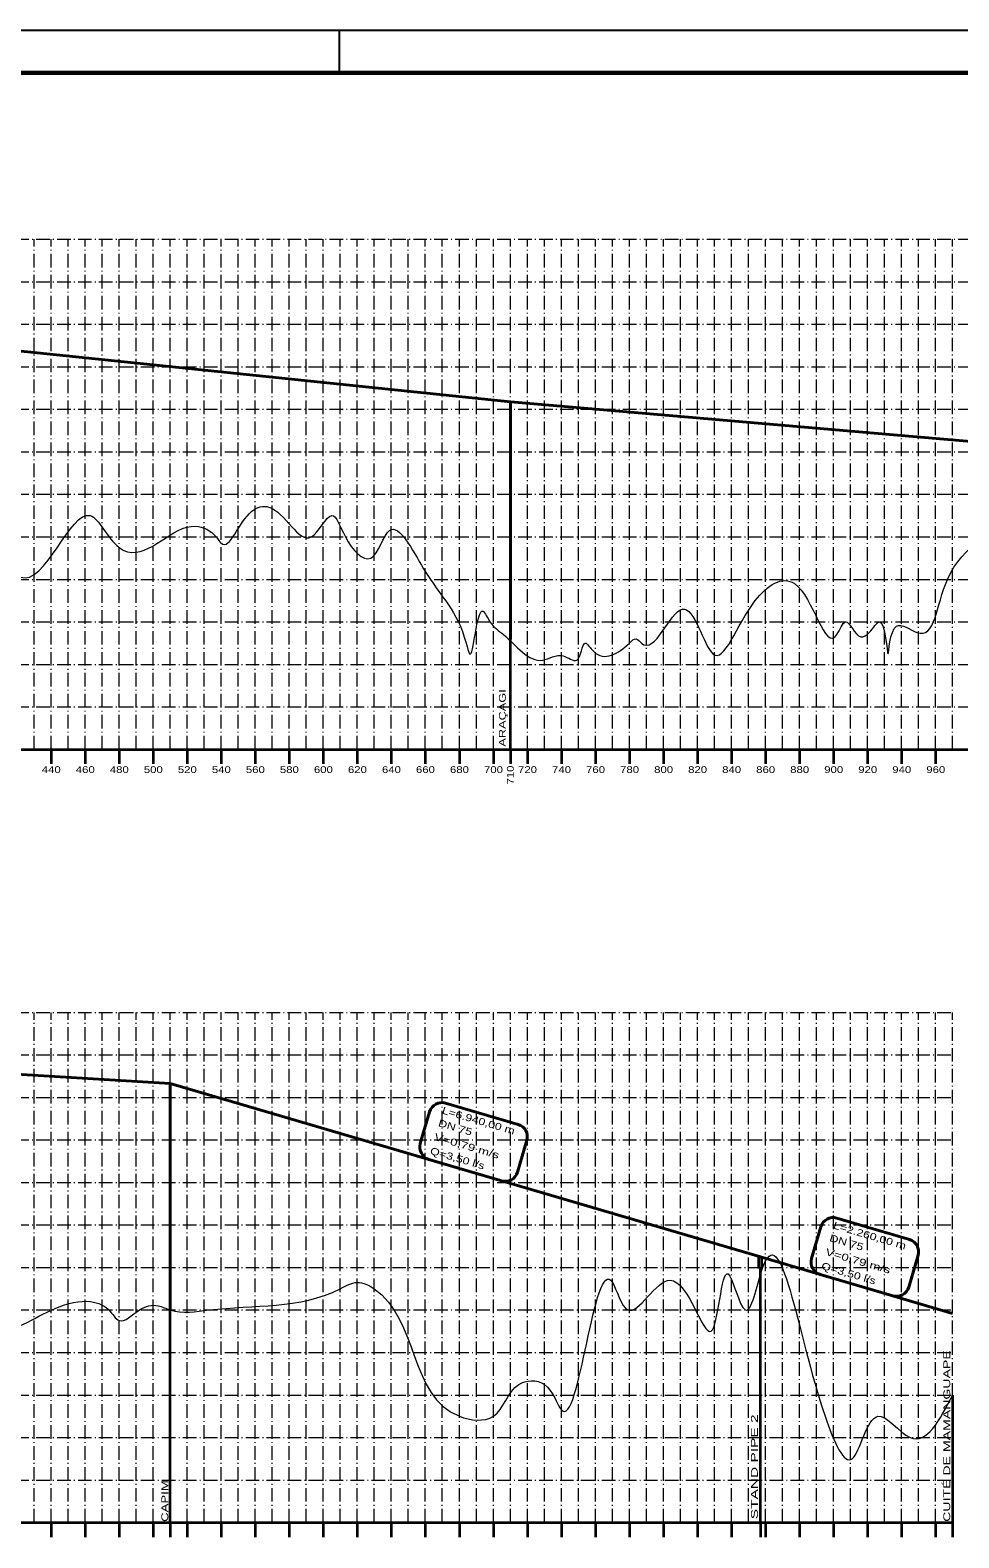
# Model space of a CAD drawing. Extents: x -4 to 42046, y -3 to 29697.
# Drawn here: x 11660 to 22579, y 11967 to 29697 of the extents above; entities that cross this region are included whole.
import ezdxf
from ezdxf.enums import TextEntityAlignment as Align

# ---------------------------------------------------------------- set-up
doc = ezdxf.new("R2010")
doc.units = 0
doc.header["$LTSCALE"] = 32
doc.linetypes.add('DOT_DASHED', pattern=[7.7, 5, -1.2, 0.3, -1.2])
for name, color, linetype, lineweight in [('1', 7, 'DOT_DASHED', 13), ('24', 7, 'Continuous', 35), ('55', 7, 'Continuous', 13), ('62', 7, 'Continuous', 13), ('63', 7, 'Continuous', 25), ('7', 7, 'Continuous', 35), ('9', 7, 'Continuous', 40)]:
    doc.layers.add(name, color=color, linetype=linetype, lineweight=lineweight)

msp = doc.modelspace()

# ---------------------------------------------------------------- linework, layer by layer
at = {"layer": '1'}
for p, q in [((3105.77, 27238.44), (32905.77, 27238.44)), ((11705.77, 21238.44), (11705.77, 27238.44)), ((11905.77, 21238.44), (11905.77, 27238.44)), ((12105.77, 21238.44), (12105.77, 27238.44)), ((12305.77, 21238.44), (12305.77, 27238.44)), ((12505.77, 21238.44), (12505.77, 27238.44)), ((12705.77, 21238.44), (12705.77, 27238.44)), ((12905.77, 21238.44), (12905.77, 27238.44)), ((13105.77, 21238.44), (13105.77, 27238.44)), ((13305.77, 21238.44), (13305.77, 27238.44)), ((13505.77, 21238.44), (13505.77, 27238.44)), ((13705.77, 21238.44), (13705.77, 27238.44)), ((13905.77, 21238.44), (13905.77, 27238.44)), ((14105.77, 21238.44), (14105.77, 27238.44)), ((14305.77, 21238.44), (14305.77, 27238.44)), ((14505.77, 21238.44), (14505.77, 27238.44)), ((14705.77, 21238.44), (14705.77, 27238.44)), ((14905.77, 21238.44), (14905.77, 27238.44)), ((15105.77, 21238.44), (15105.77, 27238.44)), ((15305.77, 21238.44), (15305.77, 27238.44)), ((15505.77, 21238.44), (15505.77, 27238.44)), ((15705.77, 21238.44), (15705.77, 27238.44)), ((15905.77, 21238.44), (15905.77, 27238.44)), ((16105.77, 21238.44), (16105.77, 27238.44)), ((16305.77, 21238.44), (16305.77, 27238.44)), ((16505.77, 21238.44), (16505.77, 27238.44)), ((16705.77, 21238.44), (16705.77, 27238.44)), ((16905.77, 21238.44), (16905.77, 27238.44)), ((17105.77, 21238.44), (17105.77, 27238.44)), ((17305.77, 21238.44), (17305.77, 27238.44)), ((17505.77, 21238.44), (17505.77, 27238.44)), ((17705.77, 21238.44), (17705.77, 27238.44)), ((17905.77, 21238.44), (17905.77, 27238.44)), ((18105.77, 21238.44), (18105.77, 27238.44)), ((18305.77, 21238.44), (18305.77, 27238.44)), ((18505.77, 21238.44), (18505.77, 27238.44)), ((18705.77, 21238.44), (18705.77, 27238.44)), ((18905.77, 21238.44), (18905.77, 27238.44)), ((19105.77, 21238.44), (19105.77, 27238.44)), ((19305.77, 21238.44), (19305.77, 27238.44)), ((19505.77, 21238.44), (19505.77, 27238.44)), ((19705.77, 21238.44), (19705.77, 27238.44)), ((19905.77, 21238.44), (19905.77, 27238.44)), ((20105.77, 21238.44), (20105.77, 27238.44)), ((20305.77, 21238.44), (20305.77, 27238.44)), ((20505.77, 21238.44), (20505.77, 27238.44)), ((20705.77, 21238.44), (20705.77, 27238.44)), ((20905.77, 21238.44), (20905.77, 27238.44)), ((21105.77, 21238.44), (21105.77, 27238.44)), ((21305.77, 21238.44), (21305.77, 27238.44)), ((21505.77, 21238.44), (21505.77, 27238.44)), ((21705.77, 21238.44), (21705.77, 27238.44)), ((21905.77, 21238.44), (21905.77, 27238.44)), ((22105.77, 21238.44), (22105.77, 27238.44)), ((22305.77, 21238.44), (22305.77, 27238.44)), ((22505.77, 21238.44), (22505.77, 27238.44)), ((3105.77, 26738.44), (32905.77, 26738.44)), ((3105.77, 26238.44), (32905.77, 26238.44)), ((3105.77, 25738.44), (32905.77, 25738.44)), ((3105.77, 25238.44), (32905.77, 25238.44)), ((3105.77, 24738.44), (32905.77, 24738.44)), ((3105.77, 24238.44), (32905.77, 24238.44)), ((3105.77, 23738.44), (32905.77, 23738.44)), ((3105.77, 23238.44), (32905.77, 23238.44)), ((3105.77, 22738.44), (32905.77, 22738.44)), ((3105.77, 22238.44), (32905.77, 22238.44)), ((3105.77, 21738.44), (32905.77, 21738.44)), ((3105.77, 18146.17), (22505.77, 18146.17)), ((11705.77, 12146.17), (11705.77, 18146.17)), ((11905.77, 12146.17), (11905.77, 18146.17)), ((12105.77, 12146.17), (12105.77, 18146.17)), ((12305.77, 12146.17), (12305.77, 18146.17)), ((12505.77, 12146.17), (12505.77, 18146.17)), ((12705.77, 12146.17), (12705.77, 18146.17)), ((12905.77, 12146.17), (12905.77, 18146.17)), ((13105.77, 12146.17), (13105.77, 18146.17)), ((13305.77, 12146.17), (13305.77, 18146.17)), ((13505.77, 12146.17), (13505.77, 18146.17)), ((13705.77, 12146.17), (13705.77, 18146.17)), ((13905.77, 12146.17), (13905.77, 18146.17)), ((14105.77, 12146.17), (14105.77, 18146.17)), ((14305.77, 12146.17), (14305.77, 18146.17)), ((14505.77, 12146.17), (14505.77, 18146.17)), ((14705.77, 12146.17), (14705.77, 18146.17)), ((14905.77, 12146.17), (14905.77, 18146.17)), ((15105.77, 12146.17), (15105.77, 18146.17)), ((15305.77, 12146.17), (15305.77, 18146.17)), ((15505.77, 12146.17), (15505.77, 18146.17)), ((15705.77, 12146.17), (15705.77, 18146.17)), ((15905.77, 12146.17), (15905.77, 18146.17)), ((16105.77, 12146.17), (16105.77, 18146.17)), ((16305.77, 12146.17), (16305.77, 18146.17)), ((16505.77, 12146.17), (16505.77, 18146.17)), ((16705.77, 12146.17), (16705.77, 18146.17)), ((16905.77, 12146.17), (16905.77, 18146.17)), ((17105.77, 12146.17), (17105.77, 18146.17)), ((17305.77, 12146.17), (17305.77, 18146.17)), ((17505.77, 12146.17), (17505.77, 18146.17)), ((17705.77, 12146.17), (17705.77, 18146.17)), ((17905.77, 12146.17), (17905.77, 18146.17)), ((18105.77, 12146.17), (18105.77, 18146.17)), ((18305.77, 12146.17), (18305.77, 18146.17)), ((18505.77, 12146.17), (18505.77, 18146.17)), ((18705.77, 12146.17), (18705.77, 18146.17)), ((18905.77, 12146.17), (18905.77, 18146.17)), ((19105.77, 12146.17), (19105.77, 18146.17)), ((19305.77, 12146.17), (19305.77, 18146.17)), ((19505.77, 12146.17), (19505.77, 18146.17)), ((19705.77, 12146.17), (19705.77, 18146.17)), ((19905.77, 12146.17), (19905.77, 18146.17)), ((20105.77, 12146.17), (20105.77, 18146.17)), ((20305.77, 12146.17), (20305.77, 18146.17)), ((20505.77, 12146.17), (20505.77, 18146.17)), ((20705.77, 12146.17), (20705.77, 18146.17)), ((20905.77, 12146.17), (20905.77, 18146.17)), ((21105.77, 12146.17), (21105.77, 18146.17)), ((21305.77, 12146.17), (21305.77, 18146.17)), ((21505.77, 12146.17), (21505.77, 18146.17)), ((21705.77, 12146.17), (21705.77, 18146.17)), ((21905.77, 12146.17), (21905.77, 18146.17)), ((22105.77, 12146.17), (22105.77, 18146.17)), ((22305.77, 12146.17), (22305.77, 18146.17)), ((22505.77, 12146.17), (22505.77, 18146.17)), ((3105.77, 17646.17), (22505.77, 17646.17)), ((3105.77, 17146.17), (22505.77, 17146.17)), ((3105.77, 16646.17), (22505.77, 16646.17)), ((3105.77, 16146.17), (22505.77, 16146.17)), ((3105.77, 15646.17), (22505.77, 15646.17)), ((3105.77, 15146.17), (22505.77, 15146.17)), ((3105.77, 14646.17), (22505.77, 14646.17)), ((3105.77, 14146.17), (22505.77, 14146.17)), ((3105.77, 13646.17), (22505.77, 13646.17)), ((3105.77, 13146.17), (22505.77, 13146.17)), ((3105.77, 12646.17), (22505.77, 12646.17))]:
    msp.add_line(p, q, dxfattribs=at)
at = {"layer": '24'}
for p, q in [((20245.77, 12146.17), (20245.77, 15146.53)), ((13305.77, 12146.17), (13305.77, 14646.17))]:
    msp.add_line(p, q, dxfattribs=at)
at = {"layer": '55'}
for points in [[(3105.77, 22363.44), (3345.77, 22238.44), (3395.77, 22113.44), (3445.77, 22238.44), (3485.77, 22488.44), (3525.77, 22238.44), (3676.64, 22756.56), (3717.19, 22944.93), (3805.77, 23063.44), (3905.77, 22738.44), (3965.77, 22363.44), (4225.77, 23188.44), (4625.77, 22988.44), (5145.77, 21963.44), (6165.77, 22963.44), (6365.77, 22738.44), (6545.77, 22988.44), (6945.77, 23088.44), (7145.77, 23188.44), (7685.77, 23188.44), (8005.77, 22988.44), (8205.77, 22488.44), (8245.77, 22613.44), (8285.77, 22488.44), (8705.77, 22113.44), (9065.77, 22738.44), (9685.77, 23288.44), (10205.77, 23238.44), (10545.77, 23313.44), (11345.77, 23413.44), (11545.77, 23263.44), (12365.77, 23988.44), (12705.77, 23613.44), (12805.77, 23563.44), (13605.77, 23863.44), (13845.77, 23738.44), (13905.77, 23663.44), (14265.77, 24038.44), (14465.77, 24088.44), (14965.77, 23738.44), (15205.77, 23988.44), (15365.77, 23738.44), (15665.77, 23488.44), (15885.77, 23813.44), (16285.77, 23363.44), (16785.77, 22488.44), (16825.77, 22363.44), (16985.77, 22863.44), (17065.77, 22738.44), (17225.77, 22588.44), (17685.77, 22288.44), (17925.77, 22338.44), (18085.77, 22288.44), (18185.77, 22488.44), (18285.77, 22388.44), (18705.77, 22488.44), (18785.77, 22538.44), (18845.77, 22488.44), (19325.77, 22888.44), (19685.77, 22363.44), (20185.77, 22988.44), (20645.77, 23188.44), (21145.77, 22588.44), (21245.77, 22738.44), (21425.77, 22563.44), (21525.77, 22613.44), (21645.77, 22738.44), (21745.77, 22363.44), (21845.77, 22688.44), (22085.77, 22613.44), (22445.77, 23238.44), (23265.77, 23663.44), (23585.77, 23313.44), (23905.77, 23563.44), (24365.77, 23413.44), (24725.77, 23613.44), (25545.77, 23113.44), (26045.77, 23613.44), (27245.77, 23988.44), (27705.77, 23563.44), (27905.77, 23738.44), (28085.77, 23588.44), (28605.77, 24113.44), (29205.77, 23638.44), (29325.77, 23738.44), (29405.77, 23563.44)], [(3105.77, 13671.17), (3465.77, 13796.17), (4045.77, 13396.17), (4185.77, 13471.17), (4345.77, 13396.17), (4645.77, 13146.17), (5145.77, 12471.17), (5445.77, 12521.17), (5845.77, 12396.17), (6145.77, 12446.17), (6305.77, 12496.17), (7985.77, 14171.17), (10805.77, 14571.17), (11565.77, 14471.17), (11665.77, 14521.17), (12465.77, 14721.17), (12585.77, 14646.17), (12705.77, 14521.17), (12945.77, 14646.17), (13165.77, 14696.17), (13305.77, 14646.17), (13765.77, 14646.17), (15305.77, 14896.17), (15505.77, 14971.17), (15705.77, 14896.17), (16705.77, 13396.17), (17105.77, 13396.17), (17405.77, 13771.17), (17705.77, 13771.17), (17905.77, 13471.17), (18505.77, 14971.17), (18685.77, 14646.17), (19185.77, 14996.17), (19665.77, 14396.17), (19865.77, 15071.17), (20065.77, 14646.17), (20265.77, 15124.39), (21005.77, 13396.17), (21325.77, 12896.17), (21625.77, 13396.17), (22005.77, 13146.17), (22505.77, 13646.17)]]:
    msp.add_spline(points, degree=3, dxfattribs=at)
at = {"layer": '62', "lineweight": 35}
for p, q in [((17305.77, 21238.44), (17305.77, 22536.27)), ((11905.77, 21238.44), (11905.77, 21067.76)), ((12305.77, 21238.44), (12305.77, 21067.76)), ((12705.77, 21238.44), (12705.77, 21067.76)), ((13105.77, 21238.44), (13105.77, 21067.76)), ((13505.77, 21238.44), (13505.77, 21067.76)), ((13905.77, 21238.44), (13905.77, 21067.76)), ((14305.77, 21238.44), (14305.77, 21067.76)), ((14705.77, 21238.44), (14705.77, 21067.76)), ((15105.77, 21238.44), (15105.77, 21067.76)), ((15505.77, 21238.44), (15505.77, 21067.76)), ((15905.77, 21238.44), (15905.77, 21067.76)), ((16305.77, 21238.44), (16305.77, 21067.76)), ((16705.77, 21238.44), (16705.77, 21067.76)), ((17105.77, 21238.44), (17105.77, 21067.76)), ((17305.77, 21238.44), (17305.77, 21067.76)), ((17505.77, 21238.44), (17505.77, 21067.76)), ((17905.77, 21238.44), (17905.77, 21067.76)), ((18305.77, 21238.44), (18305.77, 21067.76)), ((18705.77, 21238.44), (18705.77, 21067.76)), ((19105.77, 21238.44), (19105.77, 21067.76)), ((19505.77, 21238.44), (19505.77, 21067.76)), ((19905.77, 21238.44), (19905.77, 21067.76)), ((20305.77, 21238.44), (20305.77, 21067.76)), ((20705.77, 21238.44), (20705.77, 21067.76)), ((21105.77, 21238.44), (21105.77, 21067.76)), ((21505.77, 21238.44), (21505.77, 21067.76)), ((21905.77, 21238.44), (21905.77, 21067.76)), ((22305.77, 21238.44), (22305.77, 21067.76)), ((3105.77, 12146.17), (22505.77, 12146.17)), ((11905.77, 12146.17), (11905.77, 11975.48)), ((12305.77, 12146.17), (12305.77, 11975.48)), ((12705.77, 12146.17), (12705.77, 11975.48)), ((13105.77, 12146.17), (13105.77, 11975.48)), ((13305.77, 12146.17), (13305.77, 11975.48)), ((13505.77, 12146.17), (13505.77, 11975.48)), ((13905.77, 12146.17), (13905.77, 11975.48)), ((14305.77, 12146.17), (14305.77, 11975.48)), ((14705.77, 12146.17), (14705.77, 11975.48)), ((15105.77, 12146.17), (15105.77, 11975.48)), ((15505.77, 12146.17), (15505.77, 11975.48)), ((15905.77, 12146.17), (15905.77, 11975.48)), ((16305.77, 12146.17), (16305.77, 11975.48)), ((16705.77, 12146.17), (16705.77, 11975.48)), ((17105.77, 12146.17), (17105.77, 11975.48)), ((17505.77, 12146.17), (17505.77, 11975.48)), ((17905.77, 12146.17), (17905.77, 11975.48)), ((18305.77, 12146.17), (18305.77, 11975.48)), ((18705.77, 12146.17), (18705.77, 11975.48)), ((19105.77, 12146.17), (19105.77, 11975.48)), ((19505.77, 12146.17), (19505.77, 11975.48)), ((19905.77, 12146.17), (19905.77, 11975.48)), ((20245.77, 12146.17), (20245.77, 11975.48)), ((20305.77, 12146.17), (20305.77, 11975.48)), ((20705.77, 12146.17), (20705.77, 11975.48)), ((21105.77, 12146.17), (21105.77, 11975.48)), ((21505.77, 12146.17), (21505.77, 11975.48)), ((21905.77, 12146.17), (21905.77, 11975.48)), ((22305.77, 12146.17), (22305.77, 11975.48))]:
    msp.add_line(p, q, dxfattribs=at)
for points in [[(3105.77, 21238.44), (10105.77, 21238.44), (29905.77, 21238.44)], [(22505.77, 13646.17), (22505.77, 12146.17), (22505.77, 11975.48)]]:
    msp.add_lwpolyline(points, dxfattribs=at)
at = {"layer": '63'}
for p, q in [((-4.21, 29697.03), (42045.8, 29697.03)), ((15295.8, 29197.03), (15295.8, 29697.03))]:
    msp.add_line(p, q, dxfattribs=at)
at = {"layer": '63', "lineweight": 60}
msp.add_lwpolyline([(1245.8, 29197.03), (41545.8, 29197.03), (41545.8, 497.03), (32795.79, 497.03)], dxfattribs=at)
at = {"layer": '7'}
msp.add_line((20228.43, 15135), (20228.43, 15266.07), dxfattribs=at)
msp.add_lwpolyline([(20263.11, 15129.79), (20263.11, 15266.07), (20228.43, 15266.07)], dxfattribs=at)
at = {"layer": '9'}
for p, q in [((17305.77, 22536.27), (17305.77, 25324.19)), ((13305.77, 17311.3), (3105.77, 17921.05)), ((13305.77, 17311.3), (13305.77, 14646.17)), ((16543.1, 17079.1), (17397.79, 16827.85)), ((16356.89, 16977.49), (16246.82, 16603.07)), ((17499.4, 16641.63), (17389.33, 16267.21)), ((16348.43, 16416.86), (17203.11, 16165.61)), ((20956.89, 15625.24), (20846.82, 15250.82)), ((21143.1, 15726.85), (21997.79, 15475.6)), ((22099.4, 15289.38), (21989.33, 14914.96)), ((20948.43, 15064.61), (21803.11, 14813.36))]:
    msp.add_line(p, q, dxfattribs=at)
for points in [[(3105.77, 26870.69), (4205.77, 26681.69), (17305.77, 25324.19), (29905.77, 24238.44), (29905.77, 25414.4), (32905.77, 24663.44)], [(13305.77, 17311.3), (20245.77, 15271.17), (22505.77, 14606.8)]]:
    msp.add_lwpolyline(points, dxfattribs=at)
for centre, start, end in [((16500.8, 16935.19), 73.61838, 163.61838), ((17355.49, 16683.94), 343.61838, 73.61838), ((16390.73, 16560.77), 163.61838, 253.61838), ((17245.42, 16309.52), 253.61838, 343.61838), ((21100.8, 15582.94), 73.61838, 163.61838), ((21955.49, 15331.69), 343.61838, 73.61838), ((20990.73, 15208.52), 163.61838, 253.61838), ((21845.42, 14957.27), 253.61838, 343.61838)]:
    msp.add_arc(centre, 150, start, end, dxfattribs=at)

# ---------------------------------------------------------------- texts
at = {"layer": '24'}
for s, width, p in [('ARAÇAGI', 1.4, (17251.76, 21271.36)), ('CUITÉ DE MAMANGUAPE', 1.55, (22476.84, 12155.25)), ('STAND PIPE 2', 1.7, (20215.45, 12185.5)), ('CAPIM', 1.45, (13282.65, 12154.37))]:
    msp.add_text(s, height=80, rotation=90, dxfattribs=dict(at, width=width)).set_placement(p)
at = {"layer": '24', "width": 1.25}
for s, p in [('440', (11907.4, 20961.24)), ('460', (12307.4, 20961.24)), ('480', (12707.4, 20961.24)), ('500', (13107.4, 20961.24)), ('520', (13507.4, 20961.24)), ('540', (13907.4, 20961.24)), ('560', (14307.4, 20961.24)), ('580', (14707.4, 20961.24)), ('600', (15107.4, 20961.24)), ('620', (15507.4, 20961.24)), ('640', (15907.4, 20961.24)), ('660', (16307.4, 20961.24)), ('680', (16707.4, 20961.24)), ('700', (17107.4, 20961.24)), ('720', (17507.4, 20961.24)), ('740', (17907.4, 20961.24)), ('760', (18307.4, 20961.24)), ('780', (18707.4, 20961.24)), ('800', (19107.4, 20961.24)), ('820', (19507.4, 20961.24)), ('840', (19907.4, 20961.24)), ('860', (20307.4, 20961.24)), ('880', (20707.4, 20961.24)), ('900', (21107.4, 20961.24)), ('920', (21507.4, 20961.24)), ('940', (21907.4, 20961.24)), ('960', (22307.4, 20961.24))]:
    msp.add_text(s, height=80, dxfattribs=at).set_placement(p, align=Align.CENTER)
msp.add_text('710', height=80, rotation=90, dxfattribs=at).set_placement((17345.06, 20936.88), align=Align.CENTER)
at = {"layer": '9'}
for s, width, p in [('L=6.940,00 m', 1.3, (16494.23, 16958.52)), ('DN 75', 1.3, (16450.66, 16810.3)), ('V=0,79 m/s', 1.4, (16402.55, 16646.63)), ('Q=3,50 l/s', 1.3, (16354.44, 16482.97)), ('L=2.260,00 m', 1.3, (21094.23, 15606.27)), ('DN 75', 1.3, (21050.66, 15458.05)), ('V=0,79 m/s', 1.4, (21002.55, 15294.38)), ('Q=3,50 l/s', 1.3, (20954.44, 15130.72))]:
    msp.add_text(s, height=82.98, rotation=343.618, dxfattribs=dict(at, width=width)).set_placement(p)

doc.saveas('drawing.dxf')
